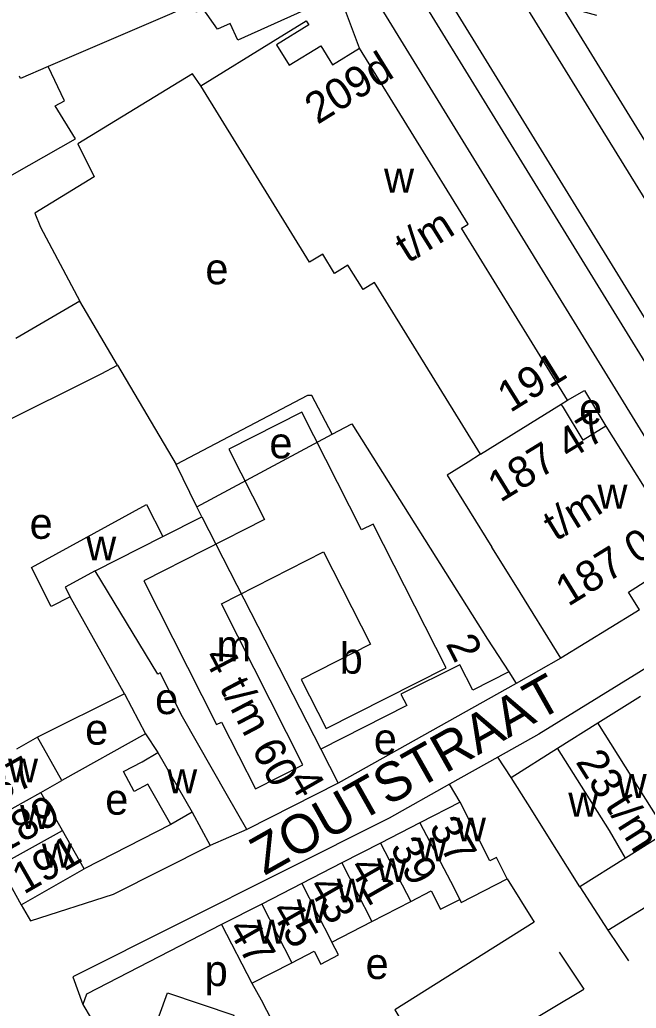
# Model space of a CAD drawing. Extents: x 159902 to 161769, y 383692 to 384875.
# Drawn here: x 160525.3 to 160604.7, y 384277.1 to 384404.5 of the extents above; entities that cross this region are included whole.
import ezdxf

# ---------------------------------------------------------------- set-up
doc = ezdxf.new("R2010")
doc.units = 0
for name, color, linetype in [('BLT_Basislijn', 7, 'Continuous'), ('BLT_Bebouwing', 7, 'Continuous'), ('BLT_Centroide', 7, 'Continuous'), ('BLT_Huisnummer', 7, 'Continuous'), ('BLT_Huisnummer_ tussenligend', 7, 'Continuous'), ('BLT_Huisnummer_reeks', 7, 'Continuous'), ('BLT_Huisnummer_zonder_bebouwing', 7, 'Continuous'), ('BLT_Onderverdeling_panden', 7, 'Continuous'), ('BLT_Plantopo', 7, 'Continuous'), ('BLT_Straatnaam', 7, 'Continuous')]:
    doc.layers.add(name, color=color, linetype=linetype)

msp = doc.modelspace()

# ---------------------------------------------------------------- linework, layer by layer
at = {"layer": 'BLT_Basislijn'}
for p, q in [((160588.59, 384409.38), (160624.95, 384350.29)), ((160569.09, 384400.82), (160566.48, 384407.73)), ((160537.9, 384359.95), (160545.45, 384347.17)), ((160548.14, 384341.7), (160545.45, 384347.17)), ((160538.81, 384317.62), (160531.79, 384330.09)), ((160595.04, 384322.18), (160589.27, 384318.95)), ((160588.31, 384320.44), (160589.27, 384318.95)), ((160589.27, 384318.95), (160566.33, 384306.11)), ((160538.81, 384317.62), (160527.57, 384312.02)), ((160538.81, 384317.62), (160541.49, 384312.43)), ((160541.49, 384312.43), (160543.1, 384310.05)), ((160592.21, 384312.4), (160586.93, 384309.44)), ((160586.93, 384309.44), (160580.68, 384305.95)), ((160588.62, 384306.83), (160586.93, 384309.44)), ((160582.04, 384303.64), (160580.68, 384305.95)), ((160547.52, 384302.35), (160549.83, 384298.06)), ((160544.79, 384300.75), (160533.61, 384295.06)), ((160554.57, 384300.13), (160549.83, 384298.06)), ((160588.13, 384293.78), (160591.61, 384288.18)), ((160601.09, 384287.15), (160603.73, 384283.18)), ((160594.82, 384284.31), (160597.98, 384279.55)), ((160555.2, 384280.3), (160556.41, 384278.16)), ((160578.74, 384268.07), (160597.98, 384279.55)), ((160556.41, 384278.16), (160561.14, 384269.02))]:
    msp.add_line(p, q, dxfattribs=at)
for points in [[(160609.76, 384337.83), (160611.06, 384340.84), (160609.15, 384344.91), (160606.34, 384350), (160546.95, 384446.54), (160528.88, 384473.45)], [(160546.58, 384460.85), (160544.3, 384459.45), (160551.15, 384449.24), (160610.66, 384352.52), (160613.6, 384347.18), (160616.84, 384340.29), (160619.41, 384341.88)], [(160619.41, 384341.88), (160616.28, 384348.55), (160613.26, 384354.03), (160553.68, 384450.86), (160550.6, 384455.44), (160547.04, 384460.09), (160546.58, 384460.85)], [(160599.65, 384405.04), (160595.1, 384406.28), (160625.48, 384357.01), (160630.61, 384355.23)], [(160548.62, 384395.97), (160547.56, 384397.5), (160532.8, 384388.47), (160534.87, 384384.22), (160527.26, 384379.54), (160527.99, 384377.73), (160533.05, 384368.2)], [(160595.87, 384355.43), (160598.09, 384356.71), (160600.81, 384352.09)], [(160565.58, 384351.07), (160562.95, 384356.07), (160562.38, 384356.03), (160545.45, 384347.17)], [(160616.32, 384327.07), (160615.38, 384326.72), (160592.21, 384312.4)], [(160541.49, 384312.43), (160530.74, 384306.45)], [(160580.68, 384305.95), (160572.92, 384301.6), (160532.14, 384281.13), (160533.41, 384277.55)], [(160525.47, 384290.4), (160526.7, 384288.34), (160537.36, 384291.8), (160549.83, 384298.06)], [(160597.5, 384292.73), (160601.09, 384287.15), (160611.79, 384293.71), (160640.61, 384248.47), (160635.26, 384246.06)], [(160551.32, 384287.88), (160533.88, 384278.88), (160533.41, 384277.55)], [(160591.61, 384288.18), (160573.65, 384276.87), (160576.03, 384272.87)], [(160539.88, 384266.74), (160544.32, 384279.06), (160552.89, 384276.18), (160550.44, 384268.6), (160548.36, 384269.25), (160542.56, 384262.25)], [(160533.41, 384277.55), (160539.88, 384266.74)]]:
    msp.add_lwpolyline(points, dxfattribs=at)
at = {"layer": 'BLT_Bebouwing'}
for p, q in [((160510.26, 384376.49), (160532.48, 384389.13)), ((160537.9, 384359.95), (160533.05, 384368.2)), ((160535.78, 384358.86), (160537.9, 384359.95)), ((160513.59, 384347.81), (160535.78, 384358.86)), ((160595.09, 384354.94), (160595.87, 384355.43)), ((160600.81, 384352.09), (160609.76, 384337.83)), ((160548.14, 384341.7), (160565.58, 384351.07)), ((160548.77, 384340.42), (160548.14, 384341.7)), ((160527.57, 384312.02), (160524.87, 384310.48)), ((160543.1, 384310.05), (160547.52, 384302.35)), ((160564.1, 384310.49), (160566.33, 384306.11)), ((160566.33, 384306.11), (160554.57, 384300.13)), ((160530.79, 384300.01), (160528.01, 384304.89)), ((160582.04, 384303.64), (160576.84, 384300.97)), ((160547.52, 384302.35), (160544.79, 384300.75)), ((160576.84, 384300.97), (160571.77, 384298.37)), ((160533.61, 384295.06), (160530.79, 384300.01)), ((160608.65, 384299.76), (160603.37, 384296.43)), ((160571.77, 384298.37), (160566.8, 384295.82)), ((160522.64, 384295.48), (160525.47, 384290.4)), ((160566.8, 384295.82), (160561.64, 384293.17)), ((160603.37, 384296.43), (160597.5, 384292.73)), ((160525.47, 384290.4), (160533.61, 384295.06)), ((160561.64, 384293.17), (160556.48, 384290.52)), ((160556.48, 384290.52), (160551.32, 384287.88)), ((160570.68, 384288.25), (160575.72, 384290.86)), ((160551.32, 384287.88), (160555.2, 384280.3)), ((160565.52, 384285.6), (160570.68, 384288.25)), ((160555.2, 384280.3), (160560.36, 384282.95))]:
    msp.add_line(p, q, dxfattribs=at)
for points in [[(160566.48, 384407.73), (160561.92, 384405.68), (160553.4, 384401.83), (160552.43, 384403.98), (160550.79, 384403.24), (160548.95, 384405.89)], [(160548.95, 384405.89), (160548.02, 384405.47), (160547.58, 384406.45), (160544.29, 384405.04), (160528.96, 384398.45)], [(160548.62, 384395.97), (160557.95, 384401.72), (160562.21, 384404.34), (160562.54, 384403.81), (160558.39, 384401.25), (160560.02, 384398.61), (160564.09, 384401.12), (160565.6, 384398.67), (160569.09, 384400.82)], [(160595.87, 384355.43), (160582.24, 384377.6), (160583.09, 384378.12), (160569.09, 384400.82)], [(160532.48, 384389.13), (160529.85, 384393.38), (160531.06, 384394.01), (160528.96, 384398.45)], [(160584.69, 384348.47), (160582.06, 384352.73), (160571.03, 384370.62), (160569.54, 384369.7), (160567.6, 384372.84), (160565.88, 384371.78), (160564.34, 384374.27), (160562.64, 384373.23), (160548.62, 384395.97)], [(160533.05, 384368.2), (160524.8, 384363.39)], [(160600.81, 384352.09), (160597.92, 384350.31), (160595.37, 384354.49), (160595.09, 384354.94)], [(160565.58, 384351.07), (160568.09, 384352.42), (160585.6, 384324.65), (160588.31, 384320.44)], [(160584.69, 384348.47), (160583.07, 384347.47), (160580.38, 384345.8), (160586.15, 384336.5)], [(160531.79, 384330.09), (160529.36, 384328.86), (160526.8, 384333.9), (160541.64, 384342.01), (160543.75, 384337.87)], [(160543.75, 384337.87), (160548.77, 384340.42)], [(160605.16, 384328.43), (160603.75, 384330.72), (160608.27, 384333.57), (160606.77, 384335.97), (160609.76, 384337.83)], [(160595.04, 384322.18), (160589.21, 384331.57), (160586.15, 384336.5)], [(160535.03, 384333.44), (160531.14, 384331.37), (160531.79, 384330.09)], [(160554.57, 384300.13), (160552.08, 384304.47), (160546.27, 384314.64), (160543.39, 384320.31), (160543.1, 384320.16), (160535.03, 384333.44)], [(160605.16, 384328.43), (160604.69, 384328.15), (160595.04, 384322.18)], [(160588.31, 384320.44), (160583.67, 384318.08), (160582.02, 384321.33), (160574.43, 384317.57), (160575.17, 384316.11), (160564.1, 384310.49)], [(160599.78, 384313.85), (160605.31, 384317.32)], [(160594.62, 384310.61), (160599.78, 384313.85)], [(160530.74, 384306.45), (160527.57, 384312.02)], [(160544.79, 384300.75), (160541.82, 384305.98), (160540.04, 384305.04), (160538.68, 384307.6), (160541.06, 384308.86), (160543.1, 384310.05)], [(160588.62, 384306.83), (160594.62, 384310.61)], [(160528.01, 384304.89), (160530.74, 384306.45)], [(160597.5, 384292.73), (160592.93, 384300), (160591.29, 384302.6), (160588.62, 384306.83)], [(160588.13, 384293.78), (160586.72, 384296.52), (160585.9, 384296.1), (160582.04, 384303.64)], [(160582, 384291.11), (160582.2, 384290.73), (160588.13, 384293.78)], [(160575.72, 384290.86), (160578.33, 384292.2), (160579.54, 384289.85), (160582, 384291.11)], [(160560.36, 384282.95), (160563.24, 384284.44), (160564.08, 384282.78), (160566.38, 384283.95), (160565.52, 384285.6)]]:
    msp.add_lwpolyline(points, dxfattribs=at)
at = {"layer": 'BLT_Onderverdeling_panden'}
for p, q in [((160584.69, 384348.47), (160595.09, 384354.94)), ((160548.77, 384340.42), (160564.1, 384310.49)), ((160535.03, 384333.44), (160543.75, 384337.87)), ((160608.65, 384299.76), (160599.78, 384313.85)), ((160519.91, 384300.39), (160528.01, 384304.89)), ((160522.64, 384295.48), (160530.79, 384300.01)), ((160571.77, 384298.37), (160575.72, 384290.86)), ((160566.8, 384295.82), (160570.68, 384288.25)), ((160561.64, 384293.17), (160565.52, 384285.6)), ((160556.48, 384290.52), (160560.36, 384282.95))]:
    msp.add_line(p, q, dxfattribs=at)
for points in [[(160528.96, 384398.45), (160525.39, 384396.92), (160525.26, 384397.19)], [(160603.37, 384296.43), (160601.3, 384300), (160594.62, 384310.61)], [(160576.84, 384300.97), (160580.79, 384293.47), (160582, 384291.11)]]:
    msp.add_lwpolyline(points, dxfattribs=at)
at = {"layer": 'BLT_Plantopo'}
msp.add_lwpolyline([(160555.68, 384305.35), (160561.8, 384308.45), (160551.28, 384329.22), (160564.46, 384335.9), (160570.5, 384323.99), (160561.57, 384319.47), (160564.79, 384313.12), (160580.24, 384320.95), (160570.85, 384339.48), (160569.36, 384338.73), (160561.67, 384353.91), (160552.23, 384349.13), (160556.82, 384340.06), (160541.27, 384332.18), (160550.66, 384313.64), (160551.32, 384313.97)], close=True, dxfattribs=at)

# ---------------------------------------------------------------- texts
at = {"layer": 'BLT_Centroide'}
for s, p in [('w', (160572.25, 384382.19)), ('e', (160549.22, 384370.38)), ('e', (160597.38, 384352.36)), ('e', (160557.47, 384347.95)), ('w', (160599.75, 384341.48)), ('e', (160526.57, 384337.58)), ('w', (160533.87, 384334.8)), ('m', (160550.67, 384321.81)), ('b', (160566.54, 384320.21)), ('e', (160542.74, 384314.99)), ('e', (160533.73, 384311.05)), ('e', (160570.93, 384309.81)), ('w', (160523.79, 384306.19)), ('w', (160544.3, 384304.8)), ('w', (160602.23, 384304.19)), ('e', (160536.32, 384302.03)), ('w', (160596, 384301.78)), ('w', (160525.35, 384300.19)), ('w', (160581.52, 384298.59)), ('w', (160528.16, 384295.22)), ('w', (160576.48, 384296)), ('w', (160571.33, 384293.34)), ('w', (160566.16, 384290.72)), ('w', (160561, 384288.06)), ('w', (160555.84, 384285.41)), ('e', (160569.87, 384280.85)), ('p', (160549.13, 384279.95))]:
    msp.add_text(s, height=4, dxfattribs=at).set_placement(p)
at = {"layer": 'BLT_Huisnummer'}
for s, rotation, p in [('2', 297.1266, (160580.14, 384324.04)), ('187', 29.0809, (160519.86, 384301.95)), ('4', 299.7437, (160559.85, 384306.52)), ('37', 299.7437, (160577.96, 384300.38)), ('191', 29.7782, (160525.82, 384291.7)), ('41', 299.7437, (160567.64, 384295.29)), ('47', 299.7437, (160552.03, 384287.35))]:
    msp.add_text(s, height=4, rotation=rotation, dxfattribs=at).set_placement(p)
at = {"layer": 'BLT_Huisnummer_ tussenligend'}
for s, rotation, p in [('189', 29.0809, (160523.01, 384296.93)), ('39', 299.7437, (160572.93, 384297.74)), ('43', 299.7437, (160562.38, 384292.8)), ('45', 299.7437, (160557.58, 384289.68))]:
    msp.add_text(s, height=4, rotation=rotation, dxfattribs=at).set_placement(p)
at = {"layer": 'BLT_Huisnummer_reeks'}
for s, rotation, p in [('209d', 31.8693, (160563.67, 384390.91)), ('t/m', 31.8755, (160575.32, 384373.03)), ('191', 31.8755, (160588.5, 384353.77)), ('187 47', 31.6119, (160587.23, 384342.2)), ('t/m', 31.6119, (160594.37, 384337.2)), ('187 01', 31.6119, (160595.97, 384328.79)), ('23', 302.1864, (160596.86, 384308.84)), ('t/m', 302.1957, (160600.64, 384303.18))]:
    msp.add_text(s, height=4, rotation=rotation, dxfattribs=at).set_placement(p)
at = {"layer": 'BLT_Huisnummer_zonder_bebouwing'}
msp.add_text('4 t/m 60', height=4, rotation=297.7437, dxfattribs=at).set_placement((160548.89, 384322.38))
at = {"layer": 'BLT_Straatnaam'}
msp.add_text('ZOUTSTRAAT', height=5, rotation=29.4464, dxfattribs=at).set_placement((160556.84, 384294.14))

doc.saveas('drawing.dxf')
